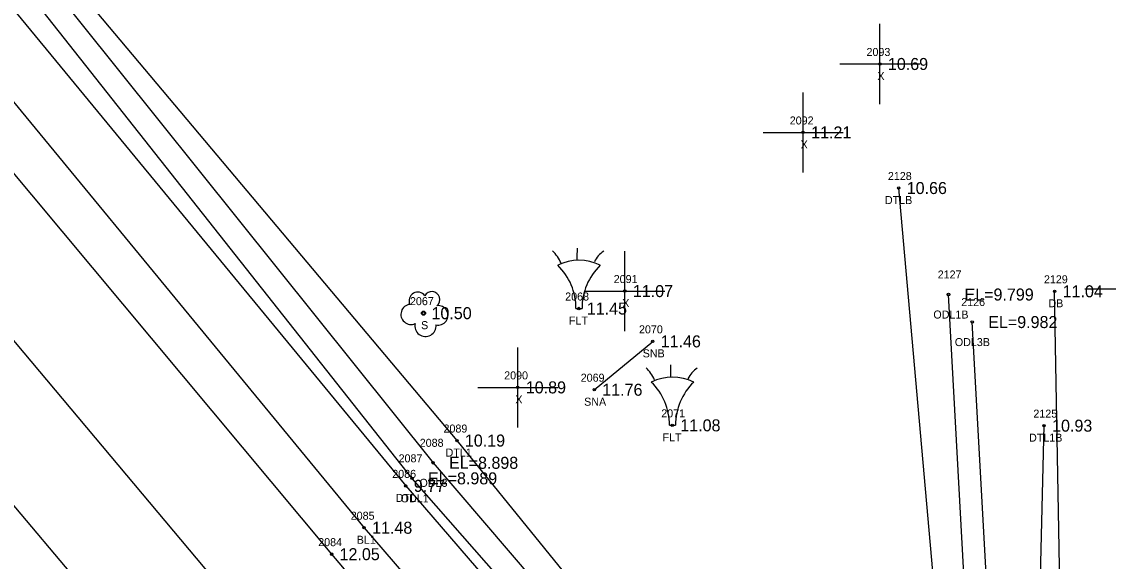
# Model space of a CAD drawing. Extents: x 2042211 to 2045853, y 303080 to 309569.
# Drawn here: x 2044230.8 to 2044366.6, y 304963.8 to 305031.1 of the extents above; entities that cross this region are included whole.
import ezdxf

# ---------------------------------------------------------------- set-up
doc = ezdxf.new("R2010")
doc.units = 0
for name, color, linetype in [('BR_500YR_SCOUR', 7, 'Continuous'), ('RD_DTM_BkLn1', 7, 'Continuous'), ('RD_DTM_BkLn_txCode', 7, 'Continuous'), ('RD_EX_BldgApp_txCode', 7, 'Continuous'), ('RD_EX_Driveway', 7, 'Continuous'), ('RD_EX_Driveway_txCode', 7, 'Continuous'), ('RD_EX_H2O', 7, 'Continuous'), ('RD_EX_H2O_txCode', 7, 'Continuous'), ('RD_EX_Misc', 7, 'Continuous'), ('RD_EX_Misc_txCode', 7, 'Continuous'), ('RD_EX_Road', 7, 'Continuous'), ('RD_EX_Road_txCode', 7, 'Continuous'), ('RD_EX_TX_BldgApp_ELEV', 7, 'Continuous'), ('RD_EX_TX_Driveway_ELEV', 7, 'Continuous'), ('RD_EX_TX_H2O_ELEV', 7, 'Continuous'), ('RD_EX_TX_Misc_ELEV', 7, 'Continuous'), ('RD_EX_TX_Road_ELEV', 7, 'Continuous'), ('RD_EX_TX_VEG_ELEV', 7, 'Continuous'), ('RD_EX_VEG_txCode', 7, 'Continuous'), ('RD_SMD_Locator', 7, 'Continuous')]:
    doc.layers.add(name, color=color, linetype=linetype)

msp = doc.modelspace()

# ---------------------------------------------------------------- linework, layer by layer
at = {"layer": 'BR_500YR_SCOUR'}
for p, q in [((2044300.07, 304995.35), (2044300.82, 304995.35)), ((2044302.35, 304985.19), (2044309.65, 304991.23)), ((2044311.75, 304980.76), (2044312.5, 304980.76))]:
    msp.add_line(p, q, dxfattribs=at)
for centre, radius in [((2044300.42, 304995.33), 0.15), ((2044281.02, 304994.75), 0.25), ((2044281.02, 304994.75), 0.15), ((2044309.65, 304991.23), 0.15), ((2044302.35, 304985.19), 0.15), ((2044312.1, 304980.74), 0.15)]:
    msp.add_circle(centre, radius, dxfattribs=at)
for centre, radius, start, end in [((2044293.75, 304998.99), 4.89, 24.3279, 46.2665), ((2044262.36, 305002.68), 37.88, 358.0671, 0.2715), ((2044305.33, 304999.74), 3.28, 123.2906, 154.4886), ((2044300.44, 304995.35), 6, 63.7794, 116.2206), ((2044292.57, 304995.35), 7.5, 0, 45.8366), ((2044308.32, 304995.35), 7.5, 134.1634, 180), ((2044280.3, 304996.3), 1.08, 34.9763, 204.756), ((2044282.07, 304996.45), 0.995, 308.7626, 152.0467), ((2044279.46, 304994.6), 1.26, 96.4518, 294.734), ((2044282.86, 304994.47), 1.22, 256.5667, 98.1046), ((2044281.27, 304993.15), 1.32, 166.8827, 5.7589), ((2044274.05, 304988.1), 37.88, 358.0671, 0.2715), ((2044305.44, 304984.4), 4.89, 24.3279, 46.2665), ((2044317.02, 304985.15), 3.28, 123.2906, 154.4886), ((2044312.13, 304980.76), 6, 63.7794, 116.2206), ((2044304.25, 304980.76), 7.5, 0, 45.8366), ((2044320, 304980.76), 7.5, 134.1634, 180)]:
    msp.add_arc(centre, radius, start, end, dxfattribs=at)
at = {"layer": 'RD_DTM_BkLn1'}
for points in [[(2043537.57, 305841.2), (2043543.07, 305834.82), (2043547.67, 305836.32), (2043557.54, 305825.5), (2043571.92, 305809.49), (2043633.83, 305732.88), (2043699.09, 305656.29), (2043762.93, 305580.55), (2043827.21, 305502.36), (2043888.69, 305425.33), (2043954.53, 305349.45), (2044014.08, 305277.47), (2044018.49, 305276.45), (2044019.61, 305275.44), (2044023.1, 305269.64), (2044024.11, 305264.85), (2044081.02, 305196.95), (2044145.48, 305121.13), (2044210.56, 305044.49), (2044273.6, 304967.95), (2044321.18, 304912.75), (2044337.82, 304895.78)], [(2043528.91, 305830.2), (2043556.35, 305797.19), (2043619.96, 305720.85), (2043684.02, 305644.21), (2043747.98, 305567.9), (2043812.35, 305491.13), (2043876, 305414.64), (2043940.22, 305337.83), (2044003.86, 305261.82), (2044067.88, 305184.94), (2044131, 305108.73), (2044195.62, 305032.03), (2044259.59, 304955.88), (2044323.63, 304879.52), (2044387.48, 304802.4), (2044451.92, 304725.21), (2044515.94, 304648.42), (2044581.15, 304571.52), (2044645.01, 304495.17), (2044708.42, 304418.52), (2044772.84, 304341.13)]]:
    msp.add_lwpolyline(points, dxfattribs=at)
at = {"layer": 'RD_EX_Driveway'}
msp.add_lwpolyline([(2044335.22, 304889.2), (2044343.52, 304892.11), (2044352.93, 304898.26), (2044359.81, 304909.65), (2044361.39, 304912.61), (2044359.86, 304997.48)], dxfattribs=at)
at = {"layer": 'RD_EX_H2O'}
for p, q in [((2044351.13, 304915.11), (2044346.6, 304997.08)), ((2044353.91, 304915), (2044349.56, 304993.64))]:
    msp.add_line(p, q, dxfattribs=at)
for points in [[(2044033.22, 305275.98), (2044035.9, 305278.5), (2044040.04, 305277.28), (2044042.29, 305273.95), (2044048.6, 305260.29), (2044090.99, 305205.39), (2044151.22, 305127.18), (2044154.78, 305124.28), (2044202.92, 305070.22), (2044216.63, 305053.71), (2044279.58, 304974.12), (2044337.99, 304907.57), (2044344.68, 304901.99)], [(2044036.31, 305275.77), (2044038.93, 305275.76), (2044040.37, 305274.17), (2044045.78, 305258.87), (2044089.4, 305204.02), (2044149.36, 305125.44), (2044152.21, 305122.89), (2044203.11, 305065.8), (2044214.18, 305051.6), (2044278.81, 304973.18), (2044336.46, 304906.31), (2044343.82, 304899.94), (2044347.6, 304901.86)], [(2044052.64, 305262.28), (2044093.07, 305207.37), (2044155.92, 305130.37), (2044157.38, 305130.75), (2044170.33, 305147.63), (2044181.38, 305159.73), (2044197.15, 305188.95), (2044208.08, 305219.28), (2044210.72, 305219.24), (2044215.12, 305217.08), (2044202.83, 305184.83), (2044185.43, 305151.79), (2044169.6, 305138.4), (2044160.58, 305125.38), (2044211.54, 305068.64), (2044219.9, 305056.44), (2044285.19, 304978.84), (2044339.94, 304911.4), (2044347.53, 304904.82), (2044347.6, 304901.86)], [(2044211.75, 305214.4), (2044200.54, 305185.5), (2044183.75, 305152.21), (2044168.79, 305139.58), (2044158.66, 305124.96), (2044210.53, 305066.67), (2044218.51, 305055.53), (2044282.21, 304976.06), (2044339.42, 304909.19), (2044345.98, 304903.69)], [(2044352.61, 304911.59), (2044348.9, 304914.63), (2044340.38, 305010.38)], [(2044352.61, 304911.59), (2044356.95, 304915.48), (2044358.54, 304980.7)]]:
    msp.add_lwpolyline(points, dxfattribs=at)
at = {"layer": 'RD_EX_Misc'}
for p, q in [((2044338.03, 305020.87), (2044338.03, 305030.87)), ((2044333.03, 305025.87), (2044343.03, 305025.87)), ((2044328.44, 305012.32), (2044328.44, 305022.32)), ((2044323.44, 305017.32), (2044333.44, 305017.32)), ((2044306.17, 304992.51), (2044306.17, 305002.51)), ((2044363.61, 304997.79), (2044373.61, 304997.79)), ((2044301.17, 304997.51), (2044311.17, 304997.51)), ((2044292.8, 304980.48), (2044292.8, 304990.48)), ((2044287.8, 304985.48), (2044297.8, 304985.48))]:
    msp.add_line(p, q, dxfattribs=at)
at = {"layer": 'RD_EX_Road'}
for points in [[(2043522.11, 305820), (2043547.67, 305789.85), (2043610.72, 305713.32), (2043674.95, 305636.32), (2043738.18, 305559.62), (2043802.42, 305482.71), (2043865.72, 305405.84), (2043929.53, 305328.85), (2043994.13, 305253.28), (2044057.4, 305176.5), (2044121.27, 305100.2), (2044185.29, 305023.54), (2044249.56, 304947.28), (2044313.31, 304870.31), (2044377.09, 304793.29), (2044442, 304716.26), (2044505.92, 304639.55), (2044570.44, 304562.35), (2044634.61, 304485.93), (2044698.46, 304409.27), (2044762.46, 304332.37)], [(2044013.41, 305270.34), (2044077.97, 305194.15), (2044141.4, 305117.67), (2044205.92, 305040.83), (2044269.54, 304964.65), (2044331.73, 304891.04), (2044335.22, 304889.2), (2044346.01, 304875.31), (2044356.18, 304867.61), (2044370.01, 304868.14), (2044386.83, 304866.36), (2044389.44, 304849.53), (2044390.71, 304830.73), (2044393.77, 304818.44), (2044395.5, 304814.18), (2044398.16, 304811.09), (2044461.8, 304734.03), (2044526.04, 304657.6), (2044591.28, 304580.23), (2044655.29, 304503.62), (2044718.26, 304427.32), (2044783.13, 304349.86)]]:
    msp.add_lwpolyline(points, dxfattribs=at)
at = {"layer": 'RD_SMD_Locator'}
for centre in [(2044338.03, 305025.87), (2044328.44, 305017.32), (2044340.38, 305010.38), (2044306.17, 304997.51), (2044346.6, 304997.08), (2044359.86, 304997.48), (2044349.56, 304993.64), (2044292.8, 304985.48), (2044358.54, 304980.7), (2044285.19, 304978.84), (2044282.21, 304976.06), (2044278.81, 304973.18), (2044279.58, 304974.12), (2044273.6, 304967.95), (2044269.54, 304964.65)]:
    msp.add_circle(centre, 0.15, dxfattribs=at)

# ---------------------------------------------------------------- texts
at = {"layer": 'RD_DTM_BkLn_txCode'}
for s, p in [('2085', (2044271.93, 304968.95)), ('BL1', (2044272.68, 304965.95))]:
    msp.add_text(s, height=1, dxfattribs=at).set_placement(p)
at = {"layer": 'RD_EX_BldgApp_txCode'}
for s, p in [('2068', (2044298.72, 304996.33)), ('FLT', (2044299.19, 304993.33)), ('2070', (2044307.94, 304992.23)), ('SNB', (2044308.4, 304989.23)), ('2069', (2044300.66, 304986.19)), ('SNA', (2044301.09, 304983.19)), ('2071', (2044310.72, 304981.74)), ('FLT', (2044310.88, 304978.74))]:
    msp.add_text(s, height=1, dxfattribs=at).set_placement(p)
at = {"layer": 'RD_EX_Driveway_txCode'}
for s, p in [('2129', (2044358.52, 304998.48)), ('DB', (2044359.08, 304995.48))]:
    msp.add_text(s, height=1, dxfattribs=at).set_placement(p)
at = {"layer": 'RD_EX_H2O_txCode'}
for s, p in [('2128', (2044339.03, 305011.38)), ('DTLB', (2044338.66, 305008.38)), ('2127', (2044345.25, 304999.08)), ('2126', (2044348.19, 304995.64)), ('ODL1B', (2044344.71, 304994.08)), ('ODL3B', (2044347.39, 304990.64)), ('2125', (2044357.2, 304981.7)), ('2089', (2044283.52, 304979.84)), ('2088', (2044280.55, 304978.06)), ('DTL1B', (2044356.66, 304978.7)), ('DTL1', (2044283.78, 304976.84)), ('2087', (2044277.91, 304976.12)), ('2086', (2044277.12, 304974.18)), ('ODL3', (2044280.52, 304973.06)), ('DTL', (2044277.56, 304971.18)), ('ODL1', (2044278.17, 304971.12))]:
    msp.add_text(s, height=1, dxfattribs=at).set_placement(p)
at = {"layer": 'RD_EX_Misc_txCode'}
for s, p in [('2093', (2044336.36, 305026.87)), ('X', (2044337.72, 305023.87)), ('2092', (2044326.77, 305018.32)), ('X', (2044328.13, 305015.32)), ('2091', (2044304.78, 304998.51)), ('X', (2044305.85, 304995.51)), ('2090', (2044291.1, 304986.48)), ('X', (2044292.49, 304983.48))]:
    msp.add_text(s, height=1, dxfattribs=at).set_placement(p)
at = {"layer": 'RD_EX_Road_txCode'}
msp.add_text('2084', height=1, dxfattribs=at).set_placement((2044267.87, 304965.65))
at = {"layer": 'RD_EX_TX_BldgApp_ELEV'}
for s, p in [('11.45', (2044301.42, 304994.58)), ('11.46', (2044310.65, 304990.48)), ('11.76', (2044303.35, 304984.44)), ('11.08', (2044313.1, 304979.99))]:
    msp.add_text(s, height=1.5, dxfattribs=at).set_placement(p)
at = {"layer": 'RD_EX_TX_Driveway_ELEV'}
msp.add_text('11.04', height=1.5, dxfattribs=at).set_placement((2044360.86, 304996.73))
at = {"layer": 'RD_EX_TX_H2O_ELEV'}
for s, p in [('10.66', (2044341.38, 305009.63)), ('EL=9.799', (2044348.6, 304996.33)), ('EL=9.982', (2044351.56, 304992.89)), ('10.93', (2044359.54, 304979.95)), ('10.19', (2044286.19, 304978.09)), ('EL=8.898', (2044284.21, 304975.31)), ('EL=8.989', (2044281.58, 304973.37)), ('9.77', (2044279.81, 304972.43))]:
    msp.add_text(s, height=1.5, dxfattribs=at).set_placement(p)
at = {"layer": 'RD_EX_TX_Misc_ELEV'}
for s, p in [('10.69', (2044339.03, 305025.12)), ('11.21', (2044329.44, 305016.57)), ('11.07', (2044307.17, 304996.76)), ('10.89', (2044293.8, 304984.73)), ('11.48', (2044274.6, 304967.2))]:
    msp.add_text(s, height=1.5, dxfattribs=at).set_placement(p)
at = {"layer": 'RD_EX_TX_Road_ELEV'}
msp.add_text('12.05', height=1.5, dxfattribs=at).set_placement((2044270.54, 304963.9))
at = {"layer": 'RD_EX_TX_VEG_ELEV'}
msp.add_text('10.50', height=1.5, dxfattribs=at).set_placement((2044282.02, 304994))
at = {"layer": 'RD_EX_VEG_txCode'}
for s, p in [('2067', (2044279.33, 304995.75)), ('S', (2044280.72, 304992.75))]:
    msp.add_text(s, height=1, dxfattribs=at).set_placement(p)

doc.saveas('drawing.dxf')
